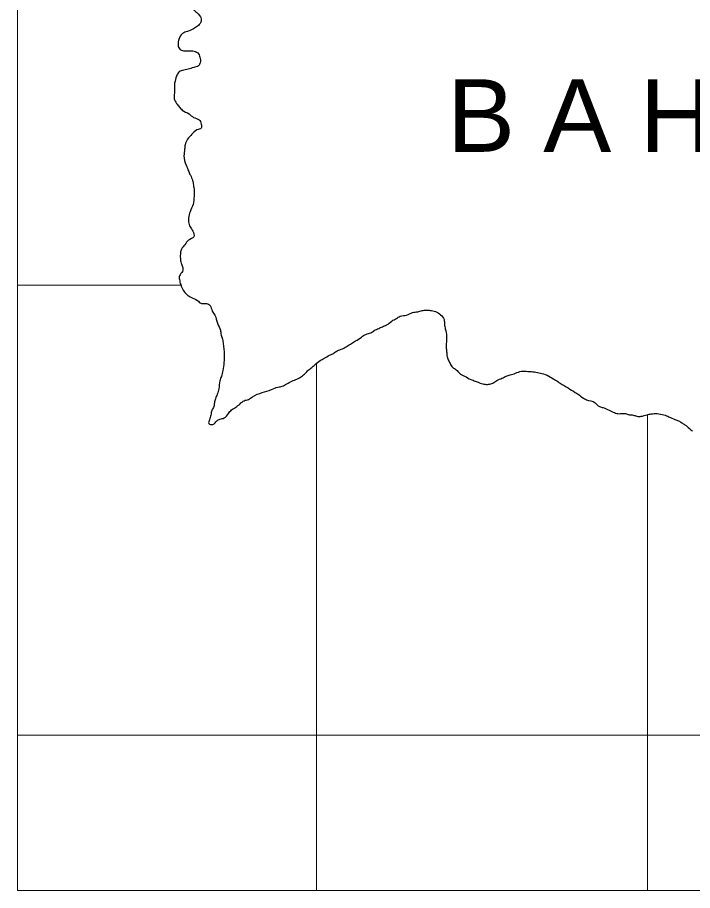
# Model space of a CAD drawing. Extents: x 854879 to 917879, y 8541948 to 8631048.
# Drawn here: x 903414 to 908252, y 8550909 to 8557163 of the extents above; entities that cross this region are included whole.
import ezdxf
from ezdxf.enums import TextEntityAlignment as Align

# ---------------------------------------------------------------- set-up
doc = ezdxf.new("R2010")
doc.units = 0
doc.header["$LTSCALE"] = 150
doc.layers.add('1', color=7, linetype='Continuous', lineweight=13)
doc.layers.add('2', color=7, linetype='Continuous', lineweight=13)

msp = doc.modelspace()

# ---------------------------------------------------------------- linework, layer by layer
at = {"layer": '1'}
for p, q in [((903413.8, 8555245.5), (904585.2, 8555245.5)), ((905557.6, 8554686.1), (905557.6, 8550908.8)), ((907928.9, 8554318.4), (907928.9, 8550908.8)), ((903413.8, 8552022.4), (909422.6, 8552022.4))]:
    msp.add_line(p, q, dxfattribs=at)
msp.add_lwpolyline([(912712.9, 8560979), (903413.8, 8560979), (903413.8, 8550908.8), (912712.9, 8550908.8)], close=True, dxfattribs=at)
at = {"layer": '1', "lineweight": 25}
for points in [[(905508.5, 8557696.7), (905475.7, 8557697.8), (905440.1, 8557722.2), (905401.5, 8557759.8), (905375.6, 8557780.5), (905353, 8557801.2), (905327.2, 8557825.1), (905304.9, 8557852.3), (905289, 8557879.3), (905266.8, 8557916.4), (905251.2, 8557953.3), (905235.7, 8558000), (905220, 8558027), (905197.8, 8558067.3), (905169, 8558101.4), (905133.8, 8558145.6), (905104.8, 8558173), (905075.6, 8558190.4), (905042.9, 8558198.2), (905006.7, 8558192.9), (904976.9, 8558184), (904943.6, 8558165.3), (904920.1, 8558143.1), (904895.9, 8558087.7), (904882.2, 8558065.1), (904865.1, 8558032.7), (904844.4, 8557987.2), (904830.6, 8557961.2), (904804, 8557942.4), (904780.7, 8557930), (904747.6, 8557917.9), (904721.3, 8557918.8), (904688.2, 8557910.1), (904661.9, 8557911), (904635.6, 8557911.9), (904609.8, 8557932.6), (904567.1, 8557934.1), (904530.2, 8557902.3), (904522.5, 8557853.1), (904521.9, 8557823.4), (904521.2, 8557793.8), (904530.5, 8557763.6), (904542.8, 8557727), (904548.8, 8557700.3), (904548.2, 8557670.7), (904544.2, 8557641), (904504.1, 8557606.2), (904477.3, 8557584), (904454, 8557571.6), (904421, 8557566.2), (904387.7, 8557550.7), (904361.1, 8557531.8), (904327.5, 8557503.4), (904313.1, 8557441.1), (904312.3, 8557404.8), (904311.6, 8557371.8), (904310.8, 8557335.5), (904336.2, 8557301.6), (904405.3, 8557302.5), (904435.1, 8557308.1), (904471.3, 8557313.4), (904504.3, 8557322.1), (904533.8, 8557317.8), (904556.6, 8557303.8), (904608.5, 8557272.3), (904631.1, 8557255.1), (904663.5, 8557230.9), (904686, 8557210.2), (904711.7, 8557186.2), (904727.7, 8557162.5), (904726.9, 8557129.6), (904703.2, 8557100.6), (904676.6, 8557081.8), (904633.4, 8557063.4), (904597, 8557048.2), (904569.7, 8557006.2), (904565.7, 8556973.3), (904571.7, 8556943.4), (904597.6, 8556926), (904627.2, 8556925), (904669.8, 8556923.6), (904705.7, 8556909.1), (904721.4, 8556878.8), (904723.9, 8556839.2), (904710.3, 8556816.4), (904677.1, 8556804.5), (904637.3, 8556792.7), (904594.4, 8556784.2), (904567.8, 8556768.6), (904554.1, 8556742.7), (904539.8, 8556693.7)], [(905508.5, 8557696.7), (905475.7, 8557697.8), (905440.1, 8557722.2), (905401.5, 8557759.8), (905375.6, 8557780.5), (905353, 8557801.2), (905327.2, 8557825.1), (905304.9, 8557852.3), (905289, 8557879.3), (905266.8, 8557916.4), (905251.2, 8557953.3), (905235.7, 8558000), (905220, 8558027), (905197.8, 8558067.3), (905169, 8558101.4), (905133.8, 8558145.6), (905104.8, 8558173), (905075.6, 8558190.4), (905042.9, 8558198.2), (905006.7, 8558192.9), (904976.9, 8558184), (904943.6, 8558165.3), (904920.1, 8558143.1), (904895.9, 8558087.7), (904882.2, 8558065.1), (904865.1, 8558032.7), (904844.4, 8557987.2), (904830.6, 8557961.2), (904804, 8557942.4), (904780.7, 8557930), (904747.6, 8557917.9), (904721.3, 8557918.8), (904688.2, 8557910.1), (904661.9, 8557911), (904635.6, 8557911.9), (904609.8, 8557932.6), (904567.1, 8557934.1), (904530.2, 8557902.3), (904522.5, 8557853.1), (904521.9, 8557823.4), (904521.2, 8557793.8), (904530.5, 8557763.6), (904542.8, 8557727), (904548.8, 8557700.3), (904548.2, 8557670.7), (904544.2, 8557641), (904504.1, 8557606.2), (904477.3, 8557584), (904454, 8557571.6), (904421, 8557566.2), (904387.7, 8557550.7), (904361.1, 8557531.8), (904327.5, 8557503.4), (904313.1, 8557441.1), (904312.3, 8557404.8), (904311.6, 8557371.8), (904310.8, 8557335.5), (904336.2, 8557301.6), (904405.3, 8557302.5), (904435.1, 8557308.1), (904471.3, 8557313.4), (904504.3, 8557322.1), (904533.8, 8557317.8), (904556.6, 8557303.8), (904608.5, 8557272.3), (904631.1, 8557255.1), (904663.5, 8557230.9), (904686, 8557210.2), (904711.7, 8557186.2), (904727.7, 8557162.5), (904726.9, 8557129.6), (904703.2, 8557100.6), (904676.6, 8557081.8), (904633.4, 8557063.4), (904597, 8557048.2), (904569.7, 8557006.2), (904565.7, 8556973.3), (904571.7, 8556943.4), (904597.6, 8556926), (904627.2, 8556925), (904669.8, 8556923.6), (904705.7, 8556909.1), (904721.4, 8556878.8), (904723.9, 8556839.2), (904710.3, 8556816.4), (904677.1, 8556804.5), (904637.3, 8556792.7), (904594.4, 8556784.2), (904567.8, 8556768.6), (904554.1, 8556742.7), (904539.8, 8556693.7)], [(904539.8, 8556693.7), (904539.3, 8556667.2), (904538.3, 8556621.1), (904537.5, 8556581.5), (904553.1, 8556548), (904572.3, 8556524.2), (904594.8, 8556500.3), (904643.4, 8556472.2), (904675.8, 8556447.9), (904714.9, 8556430.1), (904730.7, 8556399.8), (904730, 8556370.2), (904700.1, 8556357.9), (904663.3, 8556326.2), (904632.9, 8556291), (904615.6, 8556252), (904611.7, 8556219.1), (904607.3, 8556172.9), (904622.4, 8556106.4), (904641, 8556059.6), (904653.6, 8556032.7), (904669.2, 8555995.9), (904675, 8555962.6), (904680.9, 8555926.1), (904679.8, 8555883.2), (904672, 8555824), (904651.1, 8555772), (904640.3, 8555726.1), (904639.7, 8555699.7), (904652, 8555662.9), (904671.1, 8555632.7), (904676.8, 8555592.8), (904640.1, 8555567.7), (904613.2, 8555535.6), (904589.4, 8555503.4), (904582.2, 8555477.2), (904581.4, 8555437.7), (904587.2, 8555404.4), (904596.5, 8555377.7), (904595.7, 8555344.7), (904575.3, 8555312.3), (904574.8, 8555285.9), (904583.8, 8555249.3), (904628.2, 8555178.4), (904660.7, 8555157.5), (904703, 8555136.3), (904732.1, 8555115.4), (904768.2, 8555114.2), (904794.2, 8555100.1), (904809.7, 8555059.9), (904828.8, 8555029.6), (904847.3, 8554972.8), (904869.1, 8554922.5), (904871.8, 8554895.9), (904881.1, 8554865.9), (904886.9, 8554832.8), (904892.7, 8554792.9), (904895, 8554753.2), (904893.7, 8554690.6), (904885.9, 8554634.7), (904875.1, 8554592.1), (904864.4, 8554559.5), (904856.6, 8554503.6), (904846, 8554464.3), (904832.1, 8554431.8), (904824.9, 8554402.3), (904821, 8554376.1), (904807.4, 8554350.2), (904800, 8554314.1), (904789.4, 8554281.4), (904785.5, 8554255.2), (904814.9, 8554247.5), (904841.8, 8554273), (904865.1, 8554285.5), (904894.9, 8554294.3), (904925.2, 8554326.3), (904948.7, 8554351.9), (904978.7, 8554370.6), (905008.9, 8554396), (905038.9, 8554418.1), (905068.7, 8554426.9), (905098.7, 8554445.8), (905168.4, 8554476.3), (905234.6, 8554497.1), (905281, 8554515.3), (905310.6, 8554520.9), (905343.9, 8554539.5), (905380.5, 8554558.1), (905416.9, 8554573.3), (905450.2, 8554592), (905477, 8554614.1)], [(904539.8, 8556693.7), (904539.3, 8556667.2), (904538.3, 8556621.1), (904537.5, 8556581.5), (904553.1, 8556548), (904572.3, 8556524.2), (904594.8, 8556500.3), (904643.4, 8556472.2), (904675.8, 8556447.9), (904714.9, 8556430.1), (904730.7, 8556399.8), (904730, 8556370.2), (904700.1, 8556357.9), (904663.3, 8556326.2), (904632.9, 8556291), (904615.6, 8556252), (904611.7, 8556219.1), (904607.3, 8556172.9), (904622.4, 8556106.4), (904641, 8556059.6), (904653.6, 8556032.7), (904669.2, 8555995.9), (904675, 8555962.6), (904680.9, 8555926.1), (904679.8, 8555883.2), (904672, 8555824), (904651.1, 8555772), (904640.3, 8555726.1), (904639.7, 8555699.7), (904652, 8555662.9), (904671.1, 8555632.7), (904676.8, 8555592.8), (904640.1, 8555567.7), (904613.2, 8555535.6), (904589.4, 8555503.4), (904582.2, 8555477.2), (904581.4, 8555437.7), (904587.2, 8555404.4), (904596.5, 8555377.7), (904595.7, 8555344.7), (904575.3, 8555312.3), (904574.8, 8555285.9), (904583.8, 8555249.3), (904628.2, 8555178.4), (904660.7, 8555157.5), (904703, 8555136.3), (904732.1, 8555115.4), (904768.2, 8555114.2), (904794.2, 8555100.1), (904809.7, 8555059.9), (904828.8, 8555029.6), (904847.3, 8554972.8), (904869.1, 8554922.5), (904871.8, 8554895.9), (904881.1, 8554865.9), (904886.9, 8554832.8), (904892.7, 8554792.9), (904895, 8554753.2), (904893.7, 8554690.6), (904885.9, 8554634.7), (904875.1, 8554592.1), (904864.4, 8554559.5), (904856.6, 8554503.6), (904846, 8554464.3), (904832.1, 8554431.8), (904824.9, 8554402.3), (904821, 8554376.1), (904807.4, 8554350.2), (904800, 8554314.1), (904789.4, 8554281.4), (904785.5, 8554255.2), (904814.9, 8554247.5), (904841.8, 8554273), (904865.1, 8554285.5), (904894.9, 8554294.3), (904925.2, 8554326.3), (904948.7, 8554351.9), (904978.7, 8554370.6), (905008.9, 8554396), (905038.9, 8554418.1), (905068.7, 8554426.9), (905098.7, 8554445.8), (905168.4, 8554476.3), (905234.6, 8554497.1), (905281, 8554515.3), (905310.6, 8554520.9), (905343.9, 8554539.5), (905380.5, 8554558.1), (905416.9, 8554573.3), (905450.2, 8554592), (905477, 8554614.1)], [(905477, 8554614.1), (905497.3, 8554636.6), (905523.9, 8554655.4), (905544.1, 8554674.6), (905584.2, 8554706.2), (905610.9, 8554721.8), (905650.8, 8554743.5), (905680.7, 8554758.9), (905704.1, 8554774.7), (905743.9, 8554789.7), (905777.2, 8554808.5), (905807.1, 8554827.2), (905837.1, 8554845.9), (905880.5, 8554874.1), (905910.4, 8554893), (905946.8, 8554904.9), (905970.2, 8554920.5), (906003.4, 8554935.9), (906030, 8554948.2), (906059.8, 8554960.3), (906096.6, 8554988.8), (906129.9, 8555007.5), (906156.5, 8555023.1), (906202.8, 8555031.3), (906245.8, 8555049.6), (906282.1, 8555054.9), (906315.2, 8555063.8), (906341.5, 8555066.1), (906371.1, 8555065.1), (906410.4, 8555057.2), (906446, 8555032.8), (906471.5, 8554998.9), (906474.1, 8554965.8), (906480, 8554932.6), (906488.7, 8554879.4), (906487.8, 8554836.5), (906487, 8554800.3), (906489.4, 8554767.1), (906492.2, 8554740.6), (906501.4, 8554710.6), (906513.9, 8554683.8), (906533.1, 8554656.8), (906559, 8554639.3), (906581.5, 8554615.4), (906617.1, 8554594.3), (906662.6, 8554569.7), (906695.2, 8554558.6), (906721.4, 8554547.8), (906757.2, 8554536.6), (906790.1, 8554535.5), (906819.9, 8554544.4), (906849.8, 8554563.2), (906886.3, 8554578.4), (906916.2, 8554593.8), (906946, 8554602.7), (906982.4, 8554614.6), (907025.6, 8554629.7), (907071.5, 8554628), (907097.7, 8554627.1), (907140.3, 8554619.1), (907182.9, 8554611), (907234.9, 8554586), (907270.6, 8554565), (907303, 8554544), (907361.3, 8554509.1), (907410, 8554477.6), (907432.7, 8554463.7), (907465.1, 8554439.4), (907491.1, 8554425.3), (907553, 8554403.4), (907585.2, 8554375.8), (907611.3, 8554368.3), (907653.7, 8554350.3), (907692.7, 8554332.4), (907725.5, 8554324.7), (907765, 8554326.7), (907791.1, 8554319.1), (907827.1, 8554314.6), (907853.3, 8554307.1), (907882.8, 8554306), (907925.8, 8554317.7), (907955.6, 8554323.3), (907998.3, 8554325.1), (908047.4, 8554316.8), (908083.2, 8554302.4), (908125.6, 8554284.4), (908151.6, 8554273.6), (908174.4, 8554259.6), (908197, 8554245.6), (908229.4, 8554218.1), (908252, 8554200.8)], [(905477, 8554614.1), (905497.3, 8554636.6), (905523.9, 8554655.4), (905544.1, 8554674.6), (905584.2, 8554706.2), (905610.9, 8554721.8), (905650.8, 8554743.5), (905680.7, 8554758.9), (905704.1, 8554774.7), (905743.9, 8554789.7), (905777.2, 8554808.5), (905807.1, 8554827.2), (905837.1, 8554845.9), (905880.5, 8554874.1), (905910.4, 8554893), (905946.8, 8554904.9), (905970.2, 8554920.5), (906003.4, 8554935.9), (906030, 8554948.2), (906059.8, 8554960.3), (906096.6, 8554988.8), (906129.9, 8555007.5), (906156.5, 8555023.1), (906202.8, 8555031.3), (906245.8, 8555049.6), (906282.1, 8555054.9), (906315.2, 8555063.8), (906341.5, 8555066.1), (906371.1, 8555065.1), (906410.4, 8555057.2), (906446, 8555032.8), (906471.5, 8554998.9), (906474.1, 8554965.8), (906480, 8554932.6), (906488.7, 8554879.4), (906487.8, 8554836.5), (906487, 8554800.3), (906489.4, 8554767.1), (906492.2, 8554740.6), (906501.4, 8554710.6), (906513.9, 8554683.8), (906533.1, 8554656.8), (906559, 8554639.3), (906581.5, 8554615.4), (906617.1, 8554594.3), (906662.6, 8554569.7), (906695.2, 8554558.6), (906721.4, 8554547.8), (906757.2, 8554536.6), (906790.1, 8554535.5), (906819.9, 8554544.4), (906849.8, 8554563.2), (906886.3, 8554578.4), (906916.2, 8554593.8), (906946, 8554602.7), (906982.4, 8554614.6), (907025.6, 8554629.7), (907071.5, 8554628), (907097.7, 8554627.1), (907140.3, 8554619.1), (907182.9, 8554611), (907234.9, 8554586), (907270.6, 8554565), (907303, 8554544), (907361.3, 8554509.1), (907410, 8554477.6), (907432.7, 8554463.7), (907465.1, 8554439.4), (907491.1, 8554425.3), (907553, 8554403.4), (907585.2, 8554375.8), (907611.3, 8554368.3), (907653.7, 8554350.3), (907692.7, 8554332.4), (907725.5, 8554324.7), (907765, 8554326.7), (907791.1, 8554319.1), (907827.1, 8554314.6), (907853.3, 8554307.1), (907882.8, 8554306), (907925.8, 8554317.7), (907955.6, 8554323.3), (907998.3, 8554325.1), (908047.4, 8554316.8), (908083.2, 8554302.4), (908125.6, 8554284.4), (908151.6, 8554273.6), (908174.4, 8554259.6), (908197, 8554245.6), (908229.4, 8554218.1), (908252, 8554200.8)]]:
    msp.add_spline(points, degree=3, dxfattribs=at)

# ---------------------------------------------------------------- texts
at = {"layer": '2', "width": 1.05}
msp.add_text('B A H I  A', height=520, dxfattribs=at).set_placement((909698, 8556200.8), align=Align.RIGHT)

doc.saveas('drawing.dxf')
